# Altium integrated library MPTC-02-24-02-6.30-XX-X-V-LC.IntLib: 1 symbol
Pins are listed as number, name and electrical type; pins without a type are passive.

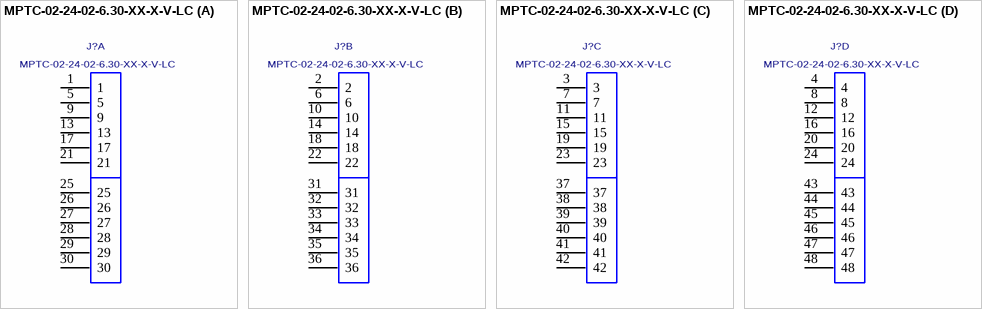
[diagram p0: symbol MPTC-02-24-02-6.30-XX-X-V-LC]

## MPTC-02-24-02-6.30-XX-X-V-LC
designator J?
VERTICAL POWER TERMINAL, 24 SIGNAL PINS, 4 POWER PINS.; MANUFACTURER: SAMTEC
footprint MPTC-02-24-02-6.30-XX-X-V-LC
part A pins: 1, 5, 9, 13, 17, 21, 25, 26, 27, 28, 29, 30
part B pins: 2, 6, 10, 14, 18, 22, 31, 32, 33, 34, 35, 36
part C pins: 3, 7, 11, 15, 19, 23, 37, 38, 39, 40, 41, 42
part D pins: 4, 8, 12, 16, 20, 24, 43, 44, 45, 46, 47, 48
